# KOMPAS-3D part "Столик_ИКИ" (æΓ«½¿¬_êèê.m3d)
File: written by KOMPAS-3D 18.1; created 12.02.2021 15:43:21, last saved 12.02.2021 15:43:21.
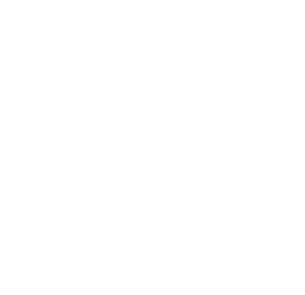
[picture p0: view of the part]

Document properties: Полное имя файла: H:\Столик\Столик_ИКИ.m3d

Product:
- Part/product: Столик_ИКИ

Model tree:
1. Операция без истории:1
